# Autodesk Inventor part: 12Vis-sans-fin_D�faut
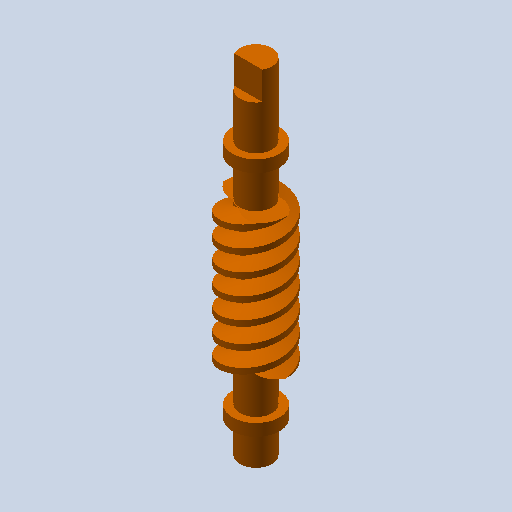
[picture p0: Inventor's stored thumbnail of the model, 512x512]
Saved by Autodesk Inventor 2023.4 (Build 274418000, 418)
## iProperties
Created: 2011-01
Part Number: 12Vis-sans-fin_D�faut
Document SubType Name: Modeling
Designer: eric
Density: 1 g/cm^3
Mass: 7.07856 g
Surface Area: 44.7397 cm^2
Volume: 7.07856 cm^3
Material: Générique
Appearance: 255,128,0_1
Author: eric
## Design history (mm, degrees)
feature "Base1"
node "Corps solides"
node "Corps surfaciques"
node "Solide1"
